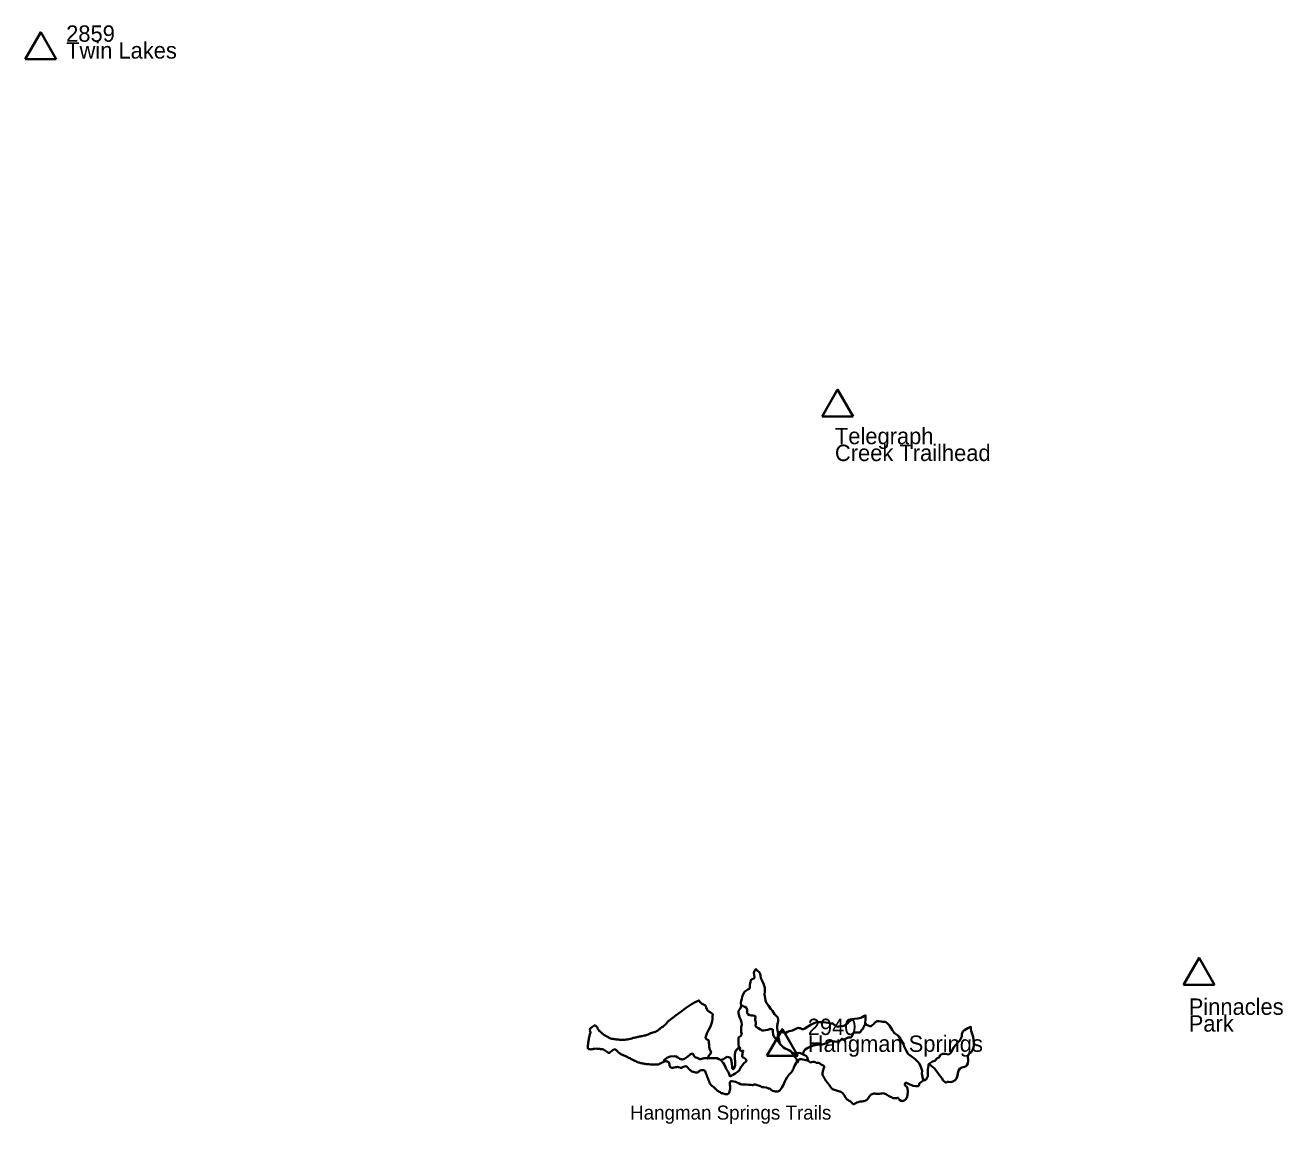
# Model space of a CAD drawing. Extents: x 322505 to 642419, y 5806860 to 5919753.
# Drawn here: x 504128 to 531026, y 5866952 to 5890451 of the extents above; entities that cross this region are included whole.
import ezdxf

# ---------------------------------------------------------------- set-up
doc = ezdxf.new("R2010")
doc.units = 0
doc.header["$LTSCALE"] = 140
for name, color, linetype, lineweight in [('1', 7, 'Continuous', 40), ('2', 7, 'Continuous', 40), ('4', 7, 'Continuous', 40)]:
    doc.layers.add(name, color=color, linetype=linetype, lineweight=lineweight)

msp = doc.modelspace()

# ---------------------------------------------------------------- linework, layer by layer
at = {"layer": '1'}
for p, q in [((504127.8, 5889723.9), (504793.2, 5889723.9)), ((519989.6, 5868403.9), (520654.9, 5868403.9))]:
    msp.add_line(p, q, dxfattribs=at)
for points in [[(504793.2, 5889723.9), (504460.5, 5890300.1), (504127.8, 5889723.9)], [(520654.9, 5868403.9), (520322.2, 5868980.1), (519989.6, 5868403.9)]]:
    msp.add_lwpolyline(points, dxfattribs=at)
at = {"layer": '2'}
for p, q in [((521171.6, 5882080.4), (521836.9, 5882080.4)), ((528900.6, 5869923.9), (529566, 5869923.9))]:
    msp.add_line(p, q, dxfattribs=at)
for points in [[(521836.9, 5882080.4), (521504.2, 5882656.6), (521171.6, 5882080.4)], [(529566, 5869923.9), (529233.3, 5870500.1), (528900.6, 5869923.9)]]:
    msp.add_lwpolyline(points, dxfattribs=at)
at = {"layer": '4'}
msp.add_line((519438.3, 5869492.2), (519432.7, 5869534.4), dxfattribs=at)
for points in [[(519432.7, 5869534.4), (519435, 5869553.2), (519441.6, 5869565.4), (519443.8, 5869586.5), (519452.7, 5869628.6), (519460.4, 5869666.3), (519481.5, 5869726.1), (519515.8, 5869772.7), (519544.6, 5869800.4), (519583.4, 5869824.8), (519614.4, 5869841.4), (519626.6, 5869855.8), (519627.7, 5869890.2), (519629.9, 5869932.3), (519641, 5869982.2), (519650.9, 5870025.4), (519675.3, 5870045.4), (519714, 5870063.9), (519725, 5870081.6), (519717.3, 5870137), (519709.5, 5870188), (519716.2, 5870204.7), (519728.4, 5870223.5), (519747.2, 5870255.6), (519764.5, 5870260.1), (519785.6, 5870232.4)], [(519785.6, 5870232.4), (519833.2, 5870192.5), (519850.9, 5870159.2), (519856.5, 5870121.5), (519863.1, 5870066.1), (519884.1, 5870021.8), (519906.3, 5869985.2), (519929.6, 5869935.3), (519945.1, 5869864.4), (519950.6, 5869793.4), (519942.8, 5869710.3), (519946.2, 5869685.9), (519963.7, 5869589.3), (519985.9, 5869536.1), (520025.8, 5869480.7), (520078.9, 5869403.1), (520111, 5869372), (520156.4, 5869300), (520224.1, 5869227.6), (520230.7, 5869186.9), (520231.8, 5869168.1), (520231.3, 5869150.9), (520224.1, 5869116.2), (520210.7, 5869051.3), (520209.6, 5868997), (520217.4, 5868947.1), (520229.5, 5868892.8), (520232.9, 5868871.7), (520227.3, 5868850.7), (520230.6, 5868824.1), (520243.9, 5868768.7), (520255, 5868733.2), (520258.3, 5868701), (520268, 5868660.7), (520294.6, 5868633), (520344.4, 5868584.2), (520382.1, 5868563.2), (520431.9, 5868545.4), (520476.2, 5868523.3), (520511.7, 5868497.8), (520542.7, 5868452.3), (520584.8, 5868394.7), (520620.2, 5868352.6), (520630.2, 5868332.6), (520630.2, 5868307.1), (520621.3, 5868267.2), (520600.3, 5868227.3), (520579.2, 5868190.7), (520567, 5868157.5), (520561.6, 5868131.8), (520549.4, 5868106.3), (520521.7, 5868064.2), (520466.3, 5868004.3), (520426.5, 5867951.1), (520393.2, 5867899), (520370, 5867844.7), (520346.7, 5867784.8), (520311.3, 5867728.3), (520268.1, 5867668.4), (520252.6, 5867656.2), (520224.9, 5867644), (520197.2, 5867640.7), (520172.8, 5867640.7), (520144, 5867649.6), (520114.1, 5867660.7), (520083.1, 5867678.4), (520070.9, 5867692.8), (520053.2, 5867706.1), (520023.6, 5867710.9)], [(517871.8, 5869141.7), (517989.8, 5869225.8), (518051.8, 5869279), (518150.4, 5869347.7), (518246.7, 5869418.7), (518377.4, 5869510.7), (518460.5, 5869556.1), (518536.9, 5869592.7), (518562.4, 5869552.8), (518591.2, 5869525.1), (518637.7, 5869502.9), (518666.5, 5869492.9), (518677.6, 5869485.2), (518686.2, 5869469.9), (518693.9, 5869438.9), (518703.9, 5869406.7), (518721.6, 5869373.5), (518749.3, 5869351.3), (518780.3, 5869338), (518805.8, 5869321.4), (518832.4, 5869295.9), (518828, 5869246), (518825.7, 5869190.6), (518822.4, 5869146.2), (518806.9, 5869095.2), (518783.6, 5869037.6), (518741.5, 5868952.6), (518703.8, 5868883.8), (518682.8, 5868820.6), (518681.7, 5868785.2), (518698.3, 5868759.7), (518730.4, 5868746.4), (518749.2, 5868732), (518752.5, 5868704.3), (518748.1, 5868680.5), (518754.8, 5868652.7), (518758.1, 5868621.7), (518760.3, 5868592.9), (518773.6, 5868541.9), (518790.2, 5868499.8), (518799.1, 5868479.8), (518795.7, 5868467.6), (518783.6, 5868448.8), (518765.8, 5868429.9), (518748.1, 5868410), (518735.9, 5868390), (518732.1, 5868352.2)], [(519724.5, 5869263.6), (519687.9, 5869269.9), (519658.9, 5869267.4), (519622.3, 5869273.7), (519586.9, 5869300.2), (519568, 5869324.2), (519563, 5869341.9), (519566.7, 5869355.8), (519573.1, 5869382.3), (519571.8, 5869393.7), (519555.4, 5869431.6), (519517.5, 5869454.3), (519486, 5869469.5), (519438.3, 5869492.2), (519435.5, 5869448), (519419.1, 5869413.9), (519383.7, 5869367.2), (519381.2, 5869321.7), (519391.3, 5869282.5), (519407.7, 5869237), (519435.5, 5869177.7), (519450.6, 5869119.6), (519453.2, 5869079.7), (519444.4, 5869017.8), (519440.6, 5868957.1), (519443.1, 5868910.4), (519453.2, 5868871.2), (519443.1, 5868848.5), (519425.4, 5868827), (519405.2, 5868814.4), (519383.8, 5868795.4), (519381.3, 5868765.1), (519382.5, 5868700.7), (519387.8, 5868648.3), (519391.6, 5868604.1), (519392.5, 5868583.9)], [(516217.6, 5868898.3), (516217.2, 5868909.1), (516202.3, 5868948.3), (516201, 5868957.8), (516209.1, 5868976.7), (516221.2, 5868995.6), (516245.6, 5869022.6), (516287.4, 5869049.7), (516304.2, 5869057.9)], [(520261.4, 5868688.1), (520255.4, 5868685.4), (520221.3, 5868735.9), (520204.9, 5868752.3), (520169.6, 5868785.2), (520134.2, 5868835.7), (520122.9, 5868868.5), (520120.3, 5868912.8), (520120.3, 5868936.8), (520117.8, 5868965.8), (520110.2, 5868975.9), (520082.5, 5868975.9), (520058.5, 5868982.2), (520032, 5868970.9), (520009.3, 5868965.8), (519965.1, 5868957), (519920.9, 5868948.1), (519905, 5868946.5), (519888.6, 5868946.5), (519873.5, 5868956.6), (519855.8, 5868968), (519800.2, 5869003.3), (519776.3, 5869017.2), (519762.4, 5869024.8), (519749.8, 5869043.8), (519748.5, 5869060.2), (519753.5, 5869086.7), (519753.5, 5869108.2), (519756.1, 5869127.1), (519748.5, 5869147.4), (519739.7, 5869175.1), (519738.4, 5869196.6), (519746, 5869218.1), (519747.2, 5869237), (519740.9, 5869253.5), (519724.5, 5869263.6)], [(520224.5, 5868915.1), (520296.3, 5868915), (520333.9, 5868910.7), (520368.6, 5868902), (520397.6, 5868902), (520432.2, 5868916.5), (520469.8, 5868932.4), (520535.9, 5868951.2), (520625.6, 5868991.7), (520661.7, 5869003.3), (520683.4, 5869001.9), (520700.8, 5868996.1), (520728.2, 5868981.6), (520747, 5868974.4), (520775.9, 5868980.2), (520802, 5868993.2), (520940.4, 5869077), (521002.6, 5869103), (521041.6, 5869119), (521079.2, 5869127.6), (521184.2, 5869124.8), (521249.3, 5869119), (521304.2, 5869108.9), (521354.8, 5869101.6), (521392.4, 5869097.3), (521406.9, 5869091.5), (521425.7, 5869077), (521448.8, 5869053.9), (521470.5, 5869038), (521487.8, 5869027.9), (521519.6, 5869033.6), (521567.4, 5869042.3), (521600.6, 5869043.8), (521635.3, 5869049.6), (521681.6, 5869066.9), (521717.3, 5869099.9), (521743.3, 5869134.7), (521789.6, 5869172.3), (521821.4, 5869194), (521864.7, 5869196.9), (521935.6, 5869202.7), (521997.8, 5869222.9), (522031, 5869231.6), (522067.1, 5869253.3), (522093.2, 5869266.3), (522103.3, 5869275), (522097.5, 5869188.2), (522096.1, 5869113), (522094.6, 5869086.9), (522109.1, 5869088.4), (522125, 5869071), (522156.8, 5869055.1), (522190, 5869042), (522220.4, 5869037.7), (522242.1, 5869059.4), (522282.6, 5869089.8), (522295.6, 5869110.1), (522324.5, 5869133.2), (522350.9, 5869146.9), (522385.6, 5869146.9), (522433.3, 5869138.2), (522473.8, 5869130.9), (522525.8, 5869132.4), (522569.2, 5869099.1), (522612.6, 5869055.7), (522671.8, 5868963.1), (522716.7, 5868899.4), (522745.6, 5868877.7), (522786.1, 5868850.2), (522816.2, 5868817.5), (522865.3, 5868743.7), (522901.5, 5868685.9), (522917.4, 5868648.2), (522930.4, 5868609.2), (522968, 5868523.8), (523005.6, 5868458.7), (523028.7, 5868432.6), (523076.4, 5868399.4), (523163.2, 5868338.6), (523215.2, 5868286.5), (523240.7, 5868254.3), (523271, 5868206.5), (523291.3, 5868151.6), (523311.5, 5868089.3), (523308.6, 5868030), (523310.1, 5867993.8), (523324.5, 5867920), (523350.6, 5867889.7), (523369.3, 5867886.8), (523399.7, 5867902.7), (523422.8, 5867943.2), (523433, 5867970.7), (523434.4, 5868040.1), (523434.4, 5868115.4), (523440.2, 5868154.5), (523446, 5868197.9), (523447.4, 5868219.6), (523472, 5868245.6), (523531.3, 5868289), (523581.9, 5868299.2), (523596.3, 5868307.8)], [(520858.2, 5868305.1), (520871.5, 5868303.2), (520851.7, 5868379.9), (520832.9, 5868405.8), (520797.4, 5868423.2), (520750.2, 5868442.5), (520768.7, 5868452.6), (520782.8, 5868507.9), (520793.6, 5868530.6), (520809.8, 5868544.7), (520863.9, 5868576.1), (520931, 5868608.6), (520985.1, 5868628.1), (521026.3, 5868637.8), (521076, 5868642.2), (521124.7, 5868649.8), (521171.3, 5868650.8), (521224.3, 5868662.7), (521256.8, 5868668.2), (521280.6, 5868676.8), (521305.5, 5868694.2), (521331, 5868715.6), (521352.6, 5868722.1), (521377.5, 5868721), (521407.8, 5868714.5), (521451.1, 5868710.2), (521497.6, 5868702.6), (521514.9, 5868704.8), (521535.5, 5868714.5), (521551.7, 5868728.6), (521579.9, 5868757.8), (521600.4, 5868775.2), (521606.9, 5868771.9), (521615.6, 5868761.1), (521628.6, 5868756.8), (521651.3, 5868757.8), (521676.2, 5868769.7), (521704.3, 5868784.9), (521731.4, 5868800.1), (521754.1, 5868800.1), (521779, 5868797.9), (521800.6, 5868805.5), (521809.3, 5868822.8), (521819, 5868845.6), (521831.8, 5868870), (521843.7, 5868891.7), (521854.5, 5868899.2), (521877.3, 5868903.6), (521920.6, 5868904.7), (521971.4, 5868909), (521988.7, 5868915.5), (522000.6, 5868926.3), (522007.1, 5868942.6), (522014.7, 5868956.6), (522030.9, 5868970.7), (522048.3, 5868993.5), (522060.2, 5869018.4), (522071, 5869042.2), (522080.7, 5869055.2), (522094.6, 5869086.9)], [(523596.3, 5868307.8), (523602.1, 5868328.1), (523629.2, 5868349.3), (523672.5, 5868373.9), (523682.6, 5868381.2), (523691.3, 5868414.4), (523715.9, 5868436.1), (523754.9, 5868449.2), (523804.1, 5868450.6), (523879.3, 5868437.6), (523916.9, 5868463.6), (523935.7, 5868483.9), (523944.3, 5868499.8), (523960.1, 5868539.8), (523990.4, 5868591.9), (524030.9, 5868645.4), (524077.2, 5868690.3), (524110.4, 5868727.9), (524136.5, 5868771.3), (524145.1, 5868798.8), (524158.1, 5868811.8), (524162.5, 5868868.2), (524184.2, 5868929), (524214.5, 5868956.5), (524286.6, 5868996.9), (524334.3, 5869018.6), (524353.1, 5869027.2), (524353.1, 5868983.8), (524358.9, 5868939), (524400.8, 5868810.2), (524412.4, 5868752.3), (524419.6, 5868664), (524418.2, 5868622.7), (524412.5, 5868585.1), (524392.2, 5868528.7), (524364.8, 5868482.4), (524340, 5868471.1), (524302.4, 5868434), (524291.8, 5868398.5), (524295, 5868307.3), (524286.8, 5868242.6), (524270.6, 5868204), (524252.5, 5868183.2), (524218.8, 5868174.1), (524158.1, 5868156.6), (524121.3, 5868137.2), (524096.2, 5868100.2), (524083.6, 5868065.5), (524065, 5867984), (524045.2, 5867923.2), (524016.4, 5867885.7), (523969.2, 5867858.6), (523925.4, 5867846.3), (523877.7, 5867851.7), (523849.7, 5867849.4), (523826.3, 5867837.9), (523814.7, 5867836.2), (523806.9, 5867842.1), (523765, 5867876.8), (523730.3, 5867928.9), (523658, 5868030.2), (523607.4, 5868099.6), (523574.2, 5868138.7), (523528.5, 5868179.1), (523488, 5868203.7), (523447.4, 5868219.6)], [(518999.2, 5868322.3), (519066.6, 5868336.1), (519087.6, 5868346.1), (519115.3, 5868373.8), (519139.7, 5868382.6), (519169.6, 5868381.5), (519196.2, 5868372.7), (519219.4, 5868349.4), (519228.3, 5868322.8), (519239.4, 5868248.5), (519251.5, 5868153.2), (519259.3, 5868132.1), (519269.3, 5868121), (519282.6, 5868132.1), (519300.3, 5868162), (519313.6, 5868204.2), (519314.7, 5868261.8), (519306.9, 5868368.2), (519309.1, 5868442.5), (519310.2, 5868473.5), (519319.1, 5868506.8), (519334.6, 5868526.7), (519353.4, 5868548.9), (519392.5, 5868583.9)], [(517783.6, 5868292.5), (517796.2, 5868313.5), (517852.4, 5868362.9), (517924.1, 5868394.9), (518012.2, 5868399.7), (518050.9, 5868391), (518087.7, 5868373.6), (518111, 5868356.1), (518130.3, 5868341.6), (518158.4, 5868334.8), (518177.8, 5868327), (518204.9, 5868333.8), (518231.1, 5868345.4), (518301.7, 5868395.8), (518353.1, 5868436.6), (518376.3, 5868449.2), (518397.6, 5868455), (518418, 5868441.4), (518429.6, 5868416.2), (518434.4, 5868396.8), (518445.1, 5868385.2), (518471.2, 5868373.6), (518499.3, 5868364.8), (518526.4, 5868349.3)], [(518526.4, 5868349.3), (518558.4, 5868333.7), (518573.5, 5868334.8), (518600.2, 5868345.3), (518642, 5868354.6), (518674.5, 5868355.8), (518698.9, 5868354.6), (518722.1, 5868350), (518747.6, 5868355.8), (518792.9, 5868355.8), (518833.6, 5868354.6), (518875.4, 5868354.6), (518904.4, 5868356.9), (518925.3, 5868353.4), (518967.1, 5868336)], [(518967.1, 5868336), (518999.2, 5868322.3), (519020.2, 5868297.5), (519040.7, 5868272.7), (519061.2, 5868246.9), (519083.6, 5868217.5), (519105, 5868164.2), (519123, 5868125.9), (519146.4, 5868083), (519163.1, 5868063.8), (519177.8, 5868035.5), (519198.5, 5867973.7), (519214.7, 5867971), (519274.7, 5868005.2), (519314.4, 5868030.1), (519357.7, 5868057), (519401.9, 5868093.5), (519421.4, 5868136.2), (519432.2, 5868167.1), (519470.4, 5868207.6), (519500.5, 5868248.7), (519518.9, 5868263.5), (519539.3, 5868276.2), (519551.1, 5868291.6), (519554.2, 5868307.6), (519538.8, 5868332.3), (519518.5, 5868350.1), (519505, 5868361.8)], [(520750.2, 5868442.5), (520709, 5868464.3), (520672.5, 5868467.7), (520628.7, 5868462.6), (520603.4, 5868451.9), (520529.6, 5868471.5)], [(520618.7, 5868262.2), (520637.3, 5868267.4), (520662.2, 5868296.6), (520683.8, 5868328.1), (520696.8, 5868335.6), (520722.8, 5868336.7), (520858.2, 5868305.1)], [(521206.5, 5868194.4), (521153.1, 5868219.3), (521128.5, 5868236.7), (521114, 5868248.2), (521096.7, 5868255.5), (521064.9, 5868258.4), (521046.1, 5868258.4), (521021.5, 5868268.5), (521001.3, 5868277.2), (520981, 5868277.2), (520943.4, 5868271.4), (520923.2, 5868267), (520900.1, 5868275.9), (520871.5, 5868303.2)], [(519690.6, 5867776.6), (519687.3, 5867776), (519649.6, 5867783.8), (519600.7, 5867788.9), (519556.3, 5867791.9), (519543.9, 5867794), (519500.7, 5867795), (519457.3, 5867796.9), (519428.6, 5867802.3), (519388.1, 5867818.7), (519369.3, 5867825.3), (519341.6, 5867841.1), (519317.4, 5867850.4), (519287.9, 5867855.6), (519242.1, 5867865.6), (519233.6, 5867867.3), (519220.8, 5867865.5), (519207.3, 5867849.3)], [(519840.5, 5867762.3), (519833.1, 5867767.3), (519785.8, 5867779.6), (519748.7, 5867791.6), (519730.2, 5867796), (519712.9, 5867796), (519700.5, 5867778.9), (519697, 5867776.7), (519690.6, 5867776.6)], [(520023.6, 5867710.9), (520010.8, 5867717.5), (519972.9, 5867728.8), (519923.2, 5867735.9), (519898, 5867737.8), (519890.3, 5867739.6), (519840.5, 5867762.3)], [(523350.6, 5867889.7), (523278.9, 5867838.2), (523255.9, 5867818.7), (523239.5, 5867773.9), (523226.7, 5867757.4), (523179.6, 5867756.6), (523121.9, 5867763.8), (523036.6, 5867799.5), (522976.7, 5867828), (522956, 5867826.6), (522942.2, 5867810), (522939.7, 5867790.4), (522951.2, 5867773.2), (522984, 5867742.3), (522998.7, 5867709.3), (523003.9, 5867641.3), (522999.8, 5867563.2), (522981.5, 5867508.2), (522955.5, 5867470.5), (522925.4, 5867448), (522881.7, 5867438.1), (522860.1, 5867441.9), (522829.9, 5867466.5), (522806.7, 5867495.2), (522807.8, 5867505.7)]]:
    msp.add_lwpolyline(points, dxfattribs=at)
for points in [[(516304.2, 5869057.9), (516339.9, 5869044.3), (516372.2, 5868989.6), (516404.7, 5868944.8), (516448.4, 5868903), (516497.7, 5868860.3), (516543.6, 5868832.9), (516589.1, 5868809.6), (516644.9, 5868779.2), (516704.6, 5868767.4), (516789.7, 5868754.5), (516840.7, 5868752.1), (516898, 5868751.9), (517009.8, 5868756), (517073.6, 5868768.8), (517133, 5868788.4), (517210.7, 5868806), (517284.6, 5868822.1), (517370.3, 5868839.4), (517449.4, 5868864), (517528, 5868897.4), (517631, 5868930.8), (517680.7, 5868966.8), (517724.1, 5869004), (517764.1, 5869030.3), (517796.3, 5869051.9), (517834.4, 5869090), (517872.1, 5869142.1)], [(516217.6, 5868898.3), (516183.7, 5868776.3), (516171.5, 5868689.9), (516161.3, 5868618.6), (516160.6, 5868583.1), (516167.2, 5868559.9), (516185.2, 5868551.4), (516231.3, 5868544.5), (516303.6, 5868559.4), (516360, 5868559.7), (516433.6, 5868551.3), (516497.2, 5868540.6), (516540.1, 5868515.6), (516582.6, 5868481.9), (516617.3, 5868471.2), (516650, 5868489.9), (516682.9, 5868521.7), (516727.6, 5868546.7), (516764.3, 5868532.7), (516806.1, 5868493.4), (516836.3, 5868465.4), (516902.2, 5868428.3), (516968.4, 5868397.3), (517042.2, 5868365.9), (517108.1, 5868327.5), (517169.6, 5868298.5), (517247.6, 5868265.7), (517311.8, 5868249.4), (517390.8, 5868233.7), (517467.4, 5868226.5), (517538.7, 5868222.8), (517591.5, 5868221), (517646.8, 5868219.2), (517683, 5868229.6), (517712.4, 5868240.5), (517754.1, 5868262.7), (517788.6, 5868283.6), (517830.5, 5868289.3), (517849.3, 5868288.8), (517895.7, 5868271.4), (517907.8, 5868229.8), (517909, 5868199.7), (517921.2, 5868168.5), (517940.2, 5868155), (517980.1, 5868149.7), (518038.4, 5868164.6), (518114.6, 5868161.8), (518162.9, 5868149.9), (518189.6, 5868162.8), (518229.5, 5868181.9), (518273.2, 5868178.6), (518292.4, 5868161.4), (518336.4, 5868115.1), (518361.7, 5868090.5), (518413.7, 5868064), (518474.9, 5868051.1), (518504.9, 5868051.7), (518533.7, 5868067), (518548.3, 5868086.8), (518564.9, 5868095.9), (518602.5, 5868102.1), (518637.1, 5868101.7), (518668.8, 5868077.9), (518689, 5868032.5), (518707.2, 5867982), (518722.5, 5867942.2), (518746.2, 5867886.8), (518766.7, 5867833.5), (518782.3, 5867798.5), (518814.8, 5867768.2), (518879, 5867712.1), (518938.6, 5867660.5), (518974.1, 5867639.2), (519007.6, 5867617.9), (519038.8, 5867605.4), (519078.2, 5867594.1), (519114.1, 5867586.4), (519141.6, 5867585.6), (519165.4, 5867595.1), (519184.4, 5867620.5), (519193.9, 5867653), (519201.6, 5867678.5), (519204.3, 5867711.6), (519203.6, 5867751.4), (519200.9, 5867783.5), (519198.7, 5867803.6), (519207.3, 5867849.3)], [(519392.5, 5868583.9), (519413.1, 5868581.7), (519422.8, 5868576.8), (519422.8, 5868572.6), (519416.1, 5868559.5), (519412.9, 5868536.5), (519432.1, 5868510.4), (519465.1, 5868510.5), (519485.2, 5868516.8), (519483.2, 5868516.7), (519484.4, 5868512.7), (519474.4, 5868490.4), (519468.8, 5868456.4), (519463.3, 5868416.6), (519462.1, 5868392.5), (519482.4, 5868371.8), (519505, 5868361.8)], [(521205.2, 5868194.2), (521212.6, 5868191.4), (521199.2, 5868125.2), (521187.8, 5868073.6), (521181.3, 5868022.1), (521189, 5867989.1), (521213.6, 5867938.5), (521242.3, 5867888.1), (521283.8, 5867836), (521325.9, 5867784), (521352.8, 5867744.5), (521367.4, 5867721.7), (521391.6, 5867694.3), (521415.6, 5867683.9), (521460, 5867673), (521502.9, 5867657.8), (521549.7, 5867644.2), (521595.7, 5867622.5), (521626.9, 5867589.4), (521650, 5867558.1), (521669, 5867524.7), (521710.1, 5867470.1), (521731.7, 5867456.1), (521771.5, 5867436.7), (521793.1, 5867418.1), (521818.2, 5867384.2), (521836.9, 5867372.3), (521893.7, 5867394.3), (521940.3, 5867416.1), (521995.1, 5867430.5), (522048.4, 5867434.8), (522102.6, 5867449.3), (522137.3, 5867471.6), (522164.5, 5867511.5), (522191.4, 5867549.1), (522221.4, 5867576.2), (522262.7, 5867596.6), (522296.8, 5867598.4), (522340.9, 5867593.5), (522378.9, 5867591.7), (522432.9, 5867599.5), (522473.9, 5867605), (522523.7, 5867591.7), (522569, 5867563.3), (522610, 5867540.5), (522637.3, 5867530), (522678.1, 5867509.6), (522723, 5867498.2), (522751.2, 5867500.7), (522795.6, 5867506.6), (522809.2, 5867505.6)]]:
    msp.add_spline(points, degree=3, dxfattribs=at)

# ---------------------------------------------------------------- texts
at = {"layer": '1'}
for s, p in [('2859', (505005.4, 5890095.4)), ('Twin Lakes', (505005.4, 5889735.4)), ('2940', (520865.2, 5868851.6)), ('Hangman Springs', (520865.2, 5868491.6))]:
    msp.add_text(s, height=350, dxfattribs=at).set_placement(p)
at = {"layer": '2'}
for s, p in [('Telegraph', (521446.9, 5881487.8)), ('Creek Trailhead', (521446.9, 5881127.8)), ('Pinnacles', (529014, 5869283.2)), ('Park', (529014, 5868923.2))]:
    msp.add_text(s, height=350, dxfattribs=at).set_placement(p)
at = {"layer": '4'}
msp.add_text('Hangman Springs Trails', height=300, dxfattribs=at).set_placement((517066.5, 5867042.5))

doc.saveas('drawing.dxf')
